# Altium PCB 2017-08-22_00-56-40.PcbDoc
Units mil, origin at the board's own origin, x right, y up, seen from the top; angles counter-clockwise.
Board outline 3005 x 3005 mil, 4 copper layers (Top Layer, MidLayer1, MidLayer2, Bottom Layer); 23 components, 14 nets, 50 pads, 19 vias.
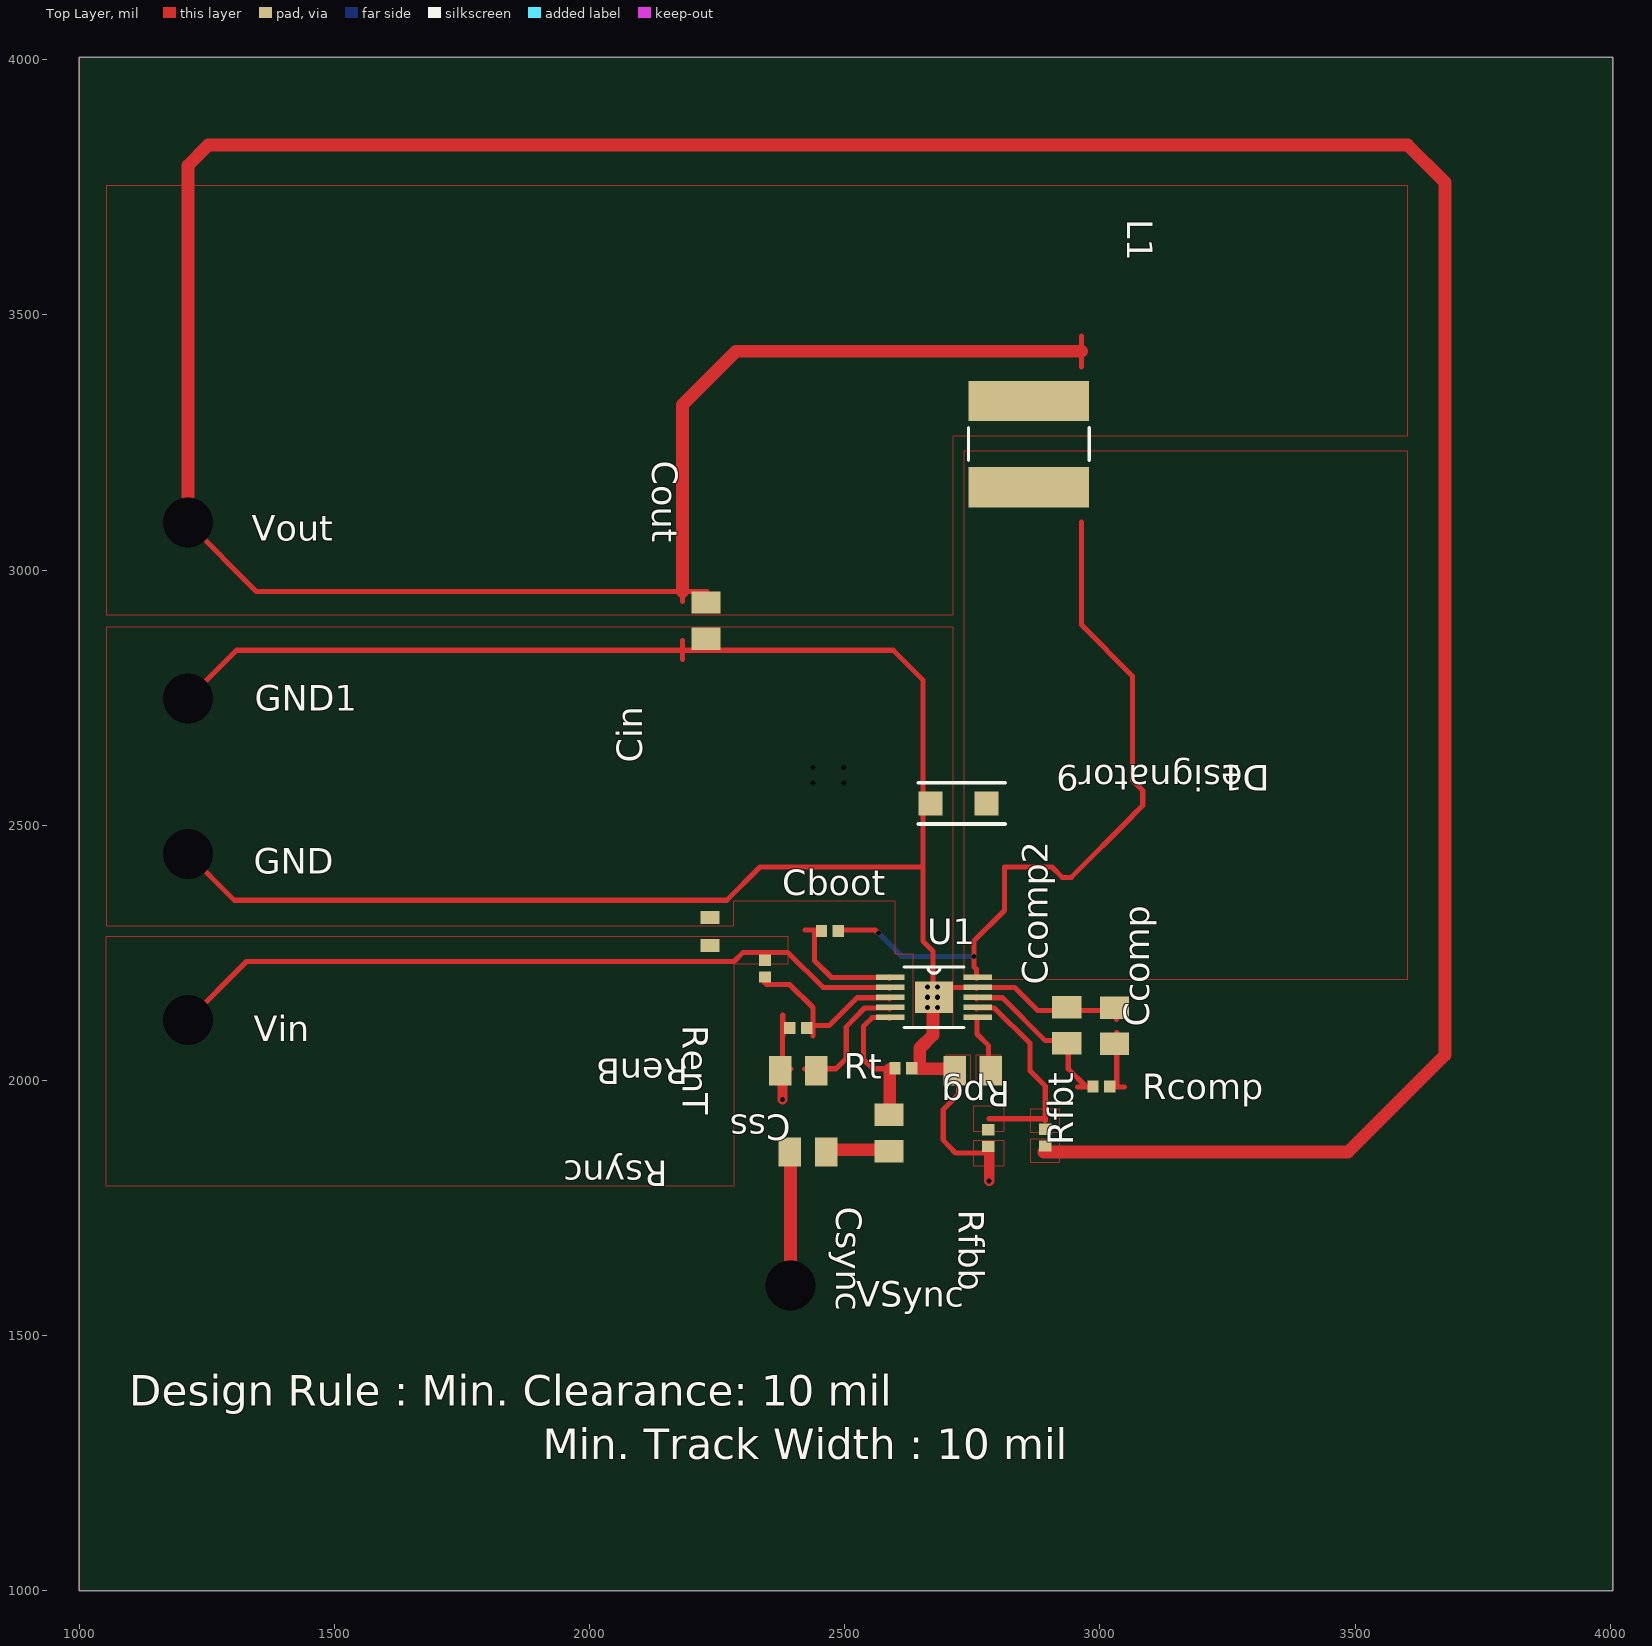
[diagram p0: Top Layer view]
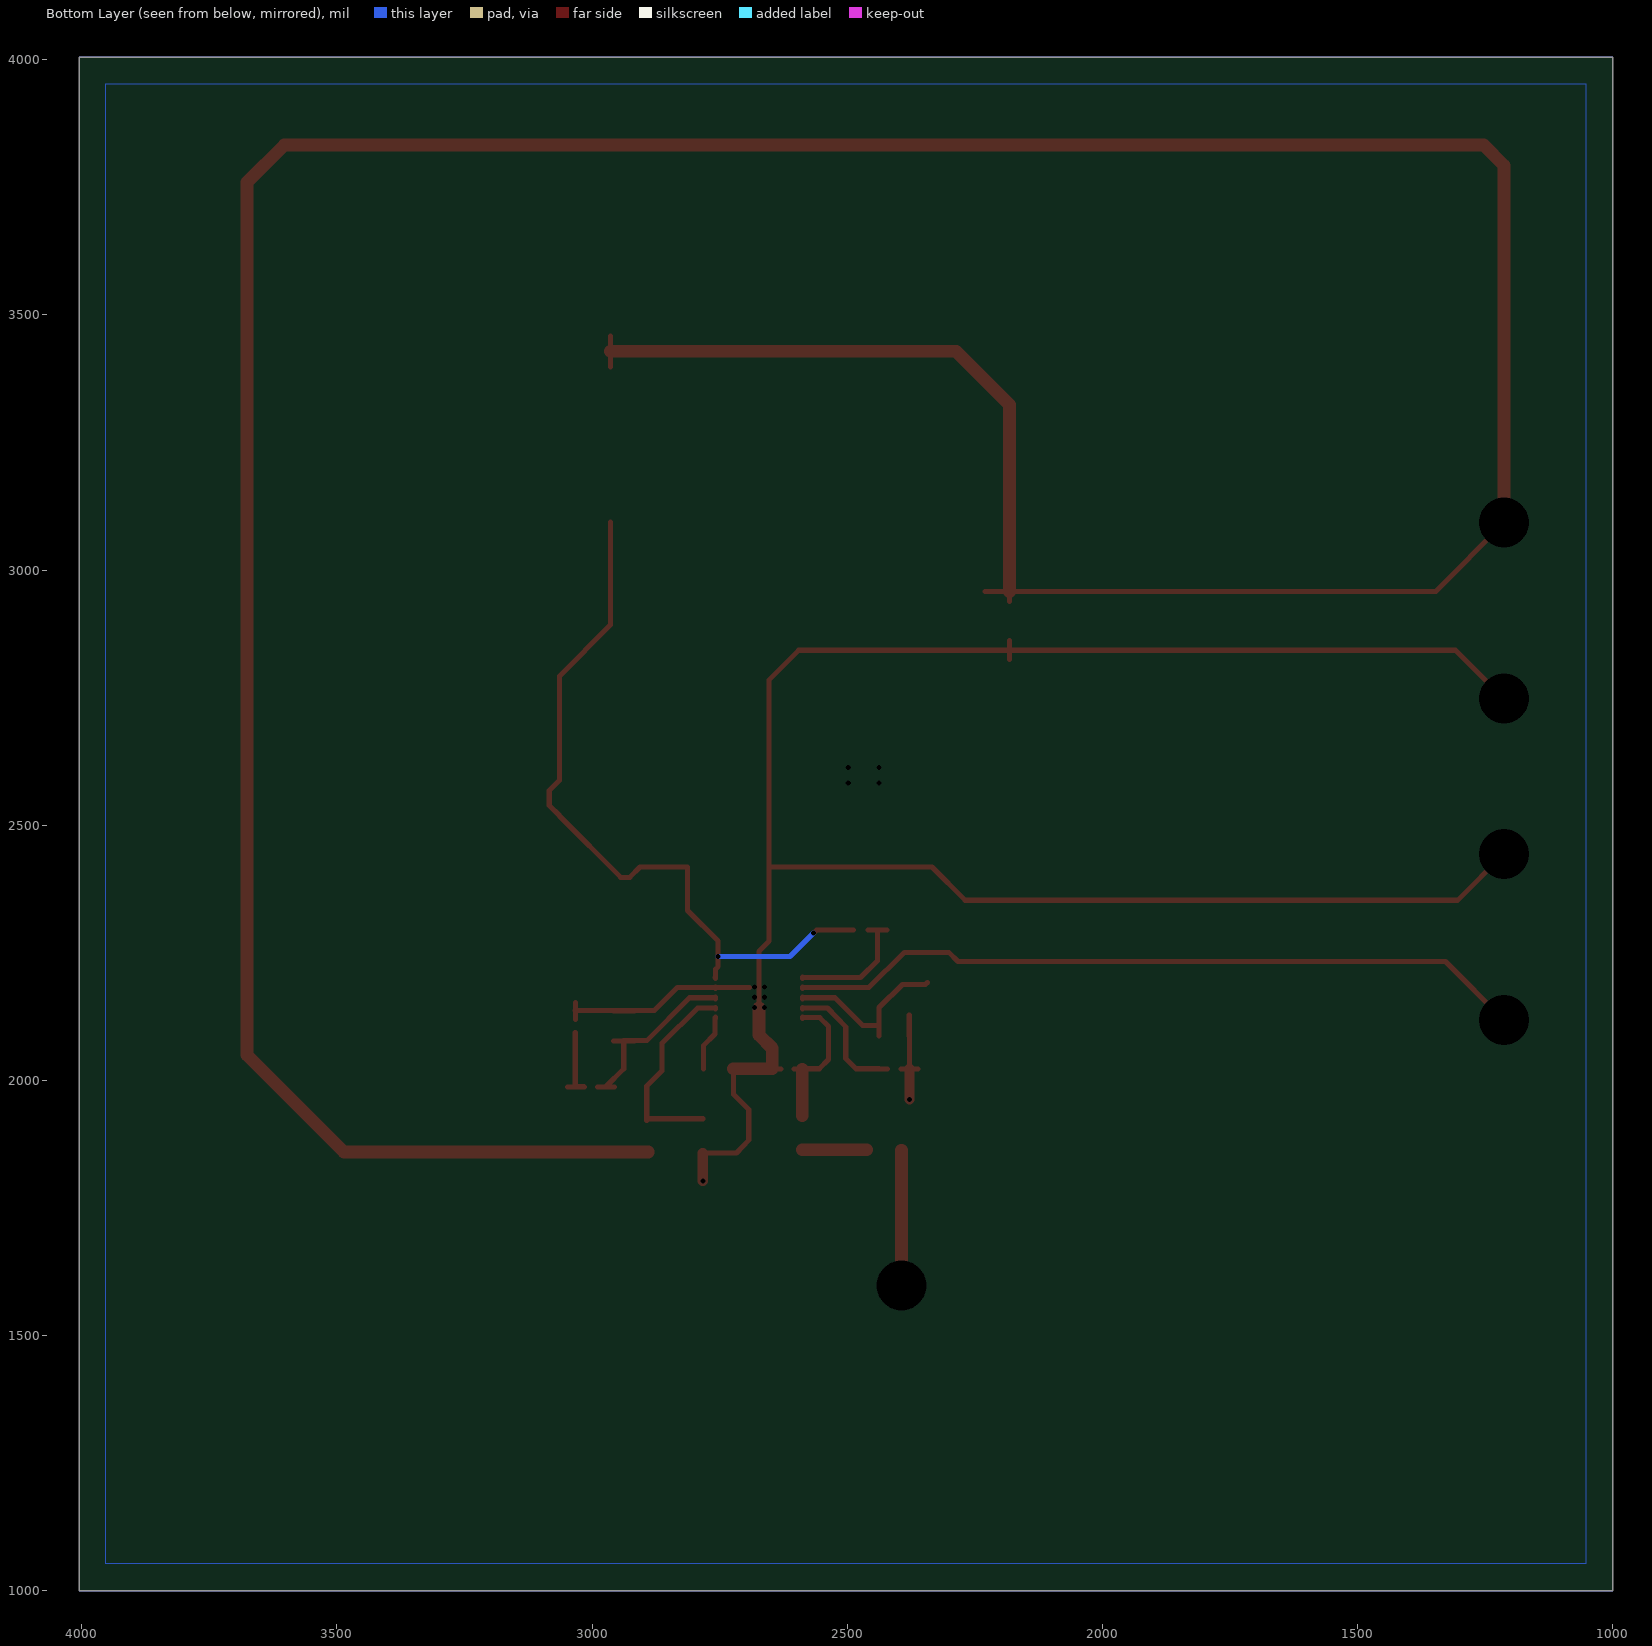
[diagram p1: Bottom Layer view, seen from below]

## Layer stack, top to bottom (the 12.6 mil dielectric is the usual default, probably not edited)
Top Layer: signal copper 1.4
Dielectric: core 12.6, FR-4, Dk 4.8
MidLayer1: signal copper 1.4
Dielectric: prepreg 12.6, FR-4, Dk 4.8
MidLayer2: signal copper 1.4
Dielectric: core 12.6, FR-4, Dk 4.8
Bottom Layer: signal copper 1.4

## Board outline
1000,1000 4005,1000 4005,4005 1000,4005

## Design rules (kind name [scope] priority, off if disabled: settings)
PlaneConnect [All] p0: scope1count=1 scope1_0_kind=Board scope1_0_value=Board scope2count=1 scope2_0_kind=Board scope2_0_value=Board commentlength=0 planeconnectstyle=Direct reliefexpansion=20 reliefentries=4 reliefconductorwidth=10 reliefairgap=10
PlaneConnect [All] p1: planeconnectstyle=Direct reliefexpansion=20 reliefentries=4 reliefconductorwidth=10 reliefairgap=10
PolygonConnect [All] p0: scope1count=1 scope1_0_kind=Board scope1_0_value=Board scope2count=1 scope2_0_kind=Board scope2_0_value=Board commentlength=0 connectstyle=Direct reliefconductorwidth=10 reliefentries=4 polygonreliefangle="90 Angle"
PolygonConnect [All] p1: connectstyle=Direct reliefconductorwidth=10 reliefentries=4 polygonreliefangle="90 Angle"

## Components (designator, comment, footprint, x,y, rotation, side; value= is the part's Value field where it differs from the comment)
Cboot "" 0402 2471,2293 r0 top
Ccomp "" 0805 3029,2107 r90 top
Ccomp2 "" 0805 2935,2108 r90 top
Cin "" 0603 2236,2292 r90 top
Cout "" 0805 2228,2901 r270 top
Css "" 0805 2409,2019 r180 top
Csync "" 0805 2587,1897 r270 top
D1 "" SOD-123F 2723,2543 r180 top
GND "" TP-1502 1212,2443 r0 top
GND1 "" TP-1502 1212,2747 r0 top
L1 "" SRN6045 2861,3247 r270 top
Rcomp "" 0402 3003,1988 r0 top
RenB "" 0402 2409,2103 r180 top
RenT "" 0402 2344,2219 r270 top
Rfbb "" 0402 2781,1887 r270 top
Rfbt "" 0402 2893,1888 r90 top
Rpg "" 0805 2751,2019 r180 top
Rsync "" 0805 2428,1860 r180 top
Rt "" 0402 2615,2024 r0 top
U1 "" S-PDSO-G10 2675,2163 r0 top
Vin "" TP-1502 1212,2117 r0 top
Vout "" TP-1502 1212,3092 r0 top
VSync "" TP-1502 2395,1594 r0 top

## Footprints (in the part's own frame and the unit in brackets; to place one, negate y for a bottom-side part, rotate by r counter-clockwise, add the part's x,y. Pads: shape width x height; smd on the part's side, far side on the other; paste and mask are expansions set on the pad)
0402 [mil]
  rect 22x24 smd: 1(-16.5,0) 2(16.5,0)
0603 [mil]
  rect 26x38 smd: 1(-27.5,0) 2(27.5,0)
0805 [mil]
  rect 44x57 smd: 1(-35.5,0) 2(35.5,0)
S-PDSO-G10 [mm]
  rect 1.411x0.27 smd: 1(-2.175,1) 2(-2.175,0.5) 3(-2.175,0) 4(-2.175,-0.5) 5(-2.175,-1) 6(2.175,-1) 7(2.175,-0.5) 8(2.175,0) 9(2.175,0.5) 10(2.175,1)
  rect 1.88x1.57 smd: 11(0,0)
  silkscreen extent -1.5,-1.5 1.5,1.5
SOD-123F [mm]
  rect 1.2x1.2 smd: 1(-1.4,0) 2(1.4,0)
  silkscreen extent -2.31,-1.03 2.01,1.03
SRN6045 [mm]
  rect 2x6 smd: 1(-2.15,0) 2(2.15,0)
  silkscreen extent -0.82,-3 0.82,3
TP-1502 [mil]
  round 65 / inner round 0 / far side round 65 hole 32: 1(0,0)

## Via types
v1: diameter 0, hole 10, Top Layer to Bottom Layer, 14 vias
v2: diameter 0, hole 98, Top Layer to Bottom Layer, 5 vias

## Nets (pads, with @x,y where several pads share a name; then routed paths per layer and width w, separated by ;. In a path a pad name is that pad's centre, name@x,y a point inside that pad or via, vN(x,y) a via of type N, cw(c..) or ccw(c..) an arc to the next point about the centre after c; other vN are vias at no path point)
0: Ccomp2.2 Ccomp.2 Cin.2 Cout.2 Css.2 D1.2 GND1.1 GND.1 RenB.2 Rfbb.2 Rpg.2 Rt.2 U1.9 U1.11 | length 4931.8
  Top Layer w10: v2(1213,2444) 1304,2353 2154,2353 2269,2353 2334,2418 2653,2418 ; v2(1213,2748) 1308,2843 2182,2843 2595,2843 2653,2785 2653,2618 2653,2617 2653,2418 ; 2182,2825 2182,2862 ; Css.2@2362,2022.5 Css.2@2395,2022.5 ; Css.2@2378,2023 2378,2108 ; 2378.5,2087 2378.5,2128 ; Rt.2@2630,2022.5 2663,2022.5 ; U1.11@2673,2136 U1.11@2673,2190 ; U1.11@2673,2163 2673,2253 2653,2273 2653,2418 ; U1.11@2692,2182 2759,2182 2833,2182 2878,2137 2938,2137 Ccomp.2@3033,2137 ; Rpg.2@2723,2023 2723,1973 2693,1943 2693,1883 2717,1858 2783,1858 ; U1.9@2758.5,2180 U1.9@2758.5,2183 ; Ccomp2.2@2917,2136.5 Ccomp2.2@2958,2136.5 ; 3032.5,2120 Ccomp.2@3032.5,2153
  Top Layer w20: v1(2378,1963) Css.2@2378,2023 ; v1(2783,1803) 2783,1858
  Top Layer w25: U1.11@2673,2142 2673,2089 2647,2063 2647,2023 Rpg.2@2723,2023
  other v1: 2662,2143 2682,2143 2662,2163 2682,2163 2662,2183 2682,2183 2438,2583 2498,2583 2438,2613 2498,2613
1: RenB.1 RenT.2 U1.3 | length 366.4
  Top Layer w10: RenT.2@2343,2192 2347,2188 2392,2188 2438,2143 2438,2108 2470,2108 2524,2162 U1.3@2588,2162 ; 2437.5,2087 2437.5,2128 ; U1.3@2587.5,2160 U1.3@2587.5,2163
2: Ccomp2.1 Rcomp.1 U1.8 | length 395.3
  Top Layer w10: U1.8@2758.5,2160 U1.8@2758.5,2163 ; U1.8@2759,2162 2809,2162 2893,2078 2938,2078 2938,2023 2973,1988 ; Ccomp2.1@2917,2077.5 Ccomp2.1@2958,2077.5 ; 2956,1987.5 Rcomp.1@2989,1987.5
3: Csync.1 Rt.1 U1.5 | length 309.5
  Top Layer w10: 2571,2022.5 Rt.1@2604,2022.5 ; U1.5@2587.5,2121 U1.5@2587.5,2124 ; Rt.1@2588,2022 2588,2023 2555,2023 2537,2041 2537,2106 2554,2123 U1.5@2588,2123
  Top Layer w25: Csync.1@2588,1931 Rt.1@2588,2022
4: Cboot.2 D1.1 L1.2 U1.10 | length 1543.6
  Top Layer w10: Cboot.2@2488,2295 2508,2295 2560,2295 v1(2566,2289) ; Cboot.2@2489,2294.5 2526,2294.5 ; U1.10@2758.5,2200 U1.10@2758.5,2203 ; U1.10@2759,2202 2758,2203 2758,2218 2753,2223 v1(2753,2243) 2753,2273 2813,2333 2813,2418 2906,2418 2926,2398 2944,2398 3064,2518 3064,2519 3084,2539 3084,2568 3064,2588 3064,2792 2964,2893 2964,3064 ; 2964,3033 2964,3094
  Bottom Layer w10: v1(2566,2289) 2612,2243 v1(2753,2243)
5: Rfbb.1 Rfbt.2 U1.7 | length 410
  Top Layer w10: U1.7@2758.5,2140 U1.7@2758.5,2143 ; U1.7@2759,2142 2793,2142 2863,2073 2863,2019 2893,1989 2893,1922 2890,1925 2783,1925
6: Cin.1 RenT.1 U1.2 Vin.1 | length 1461.4
  Top Layer w10: v2(1213,2118) 1328,2233 2154,2233 2283,2233 2301,2251 2343,2251 2388,2251 2458,2182 U1.2@2588,2182 ; U1.2@2587.5,2180 U1.2@2587.5,2183
7: Cout.1 L1.1 Rfbt.1 Vout.1 | length 8157.2
  Top Layer w10: v2(1213,3093) 1347,2958 2182,2958 Cout.1@2230,2958 ; 2182,2939 2182,2976 ; 2964,3398 2964,3459
  Top Layer w25: Vout.1@1213,3083 1213,3793 1253,3833 3603,3833 3676,3760 3676,2050 3486,1860 2890,1860 ; 2182,2958 2182,3324 2287,3429 2964,3429
8: Ccomp.1 Rcomp.2 | length 190
  Top Layer w10: Rcomp.2@3015,1987.5 3048,1987.5 ; Rcomp.2@3016,1988 3033,1988 ; 3032,1988 3033,1988 ; Ccomp.1@3032.5,2061 3032.5,2094 ; 3033,2094 3033,2078 3033,1988
9: Css.1 U1.4 | length 271.9
  Top Layer w10: 2421,2022.5 Css.1@2454,2022.5 ; Css.1@2438,2023 2483,2023 2503,2043 2503,2105 2539,2142 U1.4@2588,2142 ; U1.4@2587.5,2140 U1.4@2587.5,2143
10: Cboot.1 U1.1 | length 278
  Top Layer w10: 2422,2294.5 Cboot.1@2459,2294.5 ; 2441,2295 2442,2295 ; Cboot.1@2457,2295 2442,2295 ; U1.1@2587.5,2200 U1.1@2587.5,2203 ; U1.1@2588,2202 2474,2202 2441,2234 2441,2294 2442,2294 2442,2295
20: Rpg.1 U1.6 | length 112.5
  Top Layer w10: U1.6@2758.5,2121 U1.6@2758.5,2124 ; U1.6@2759,2123 2759,2091 2782,2068 Rpg.1@2782,2023
23: Csync.2 Rsync.1 | length 127.4
  Top Layer w10: Rsync.1@2461,1863 Rsync.1@2462,1864
  Top Layer w25: Rsync.1@2462,1864 Csync.2@2588,1864
24: Rsync.2 VSync.1 | length 265
  Top Layer w25: v2(2394,1598) Rsync.2@2394,1863

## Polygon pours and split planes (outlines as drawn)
7 on Top Layer " " (solid, pour order 0): 2865,1839 2865,1886 2920,1886 2920,1839
5 on Top Layer " " (solid, pour order 1): 2865,1898 2865,1945 2920,1945 2920,1898
5 on Top Layer " " (solid, pour order 2): 2753,1899 2753,1950 2812,1950 2812,1899
20 on Top Layer " " (solid, pour order 3): 2758,1995 2758,2050 2805,2050 2805,1995
7 on Top Layer " " (solid, pour order 4): 1053,3753 1053,2913 2713,2913 2713,3263 3603,3263 3603,3753
6 on Top Layer " " (solid, pour order 5): 1053,2283 2388,2283 2388,2228 2283,2228 2283,1793 1053,1793
4 on Top Layer " " (solid, pour order 6): 2733,2198 3603,2198 3603,3233 2733,3233
0 on Top Layer " " (solid, pour order 7): 2753,1832 2753,1883 2812,1883 2812,1832
0 on Top Layer " " (solid, pour order 8): 2699,1995 2699,2050 2746,2050 2746,1995
0 on Top Layer " " (solid, pour order 10): 1053,2303 2283,2303 2283,2352 2598,2352 2598,2248 2633,2248 2633,2103 2713,2103 2713,2888 1053,2888
0 on Bottom Layer " " (solid, pour order 9): 1053,3953 1053,1053 3953,1053 3953,3953

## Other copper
Multi-Layer:
  the board outline again, w1

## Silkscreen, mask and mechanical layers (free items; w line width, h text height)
Top Overlay:
  text "Design Rule : Min. Clearance: 10 mil" at 1098,1363 h60
  text "Min. Track Width : 10 mil" at 1908,1258 h60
